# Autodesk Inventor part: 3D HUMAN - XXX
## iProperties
Category: PART
Company: Cross Bros.
Shininess: 64.0
Length Units: 11272
Angle Units: 11279
Time Units: 11290
Mass Units: 11286
Length Display Precision: 3
Angle Display Precision: 2
Compacted: True
Part Number: 3D HUMAN - XXX
Document SubType Name: Modeling
Created: 2003-03
Designer: MVF
Catalog Web Link: www.crossbros.com
Density: 0.0
Volumn: 0.0
Area: 0.0
PropertySet Name: Model Information
Control State: 0
Master: False
Checked Out: False
Author: MVF
Title: iMike
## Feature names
1. Extrusion1
2. Extrusion2
3. Fillet2
4. Fillet3
5. Revolution1
6. Revolution2
7. Fillet1
